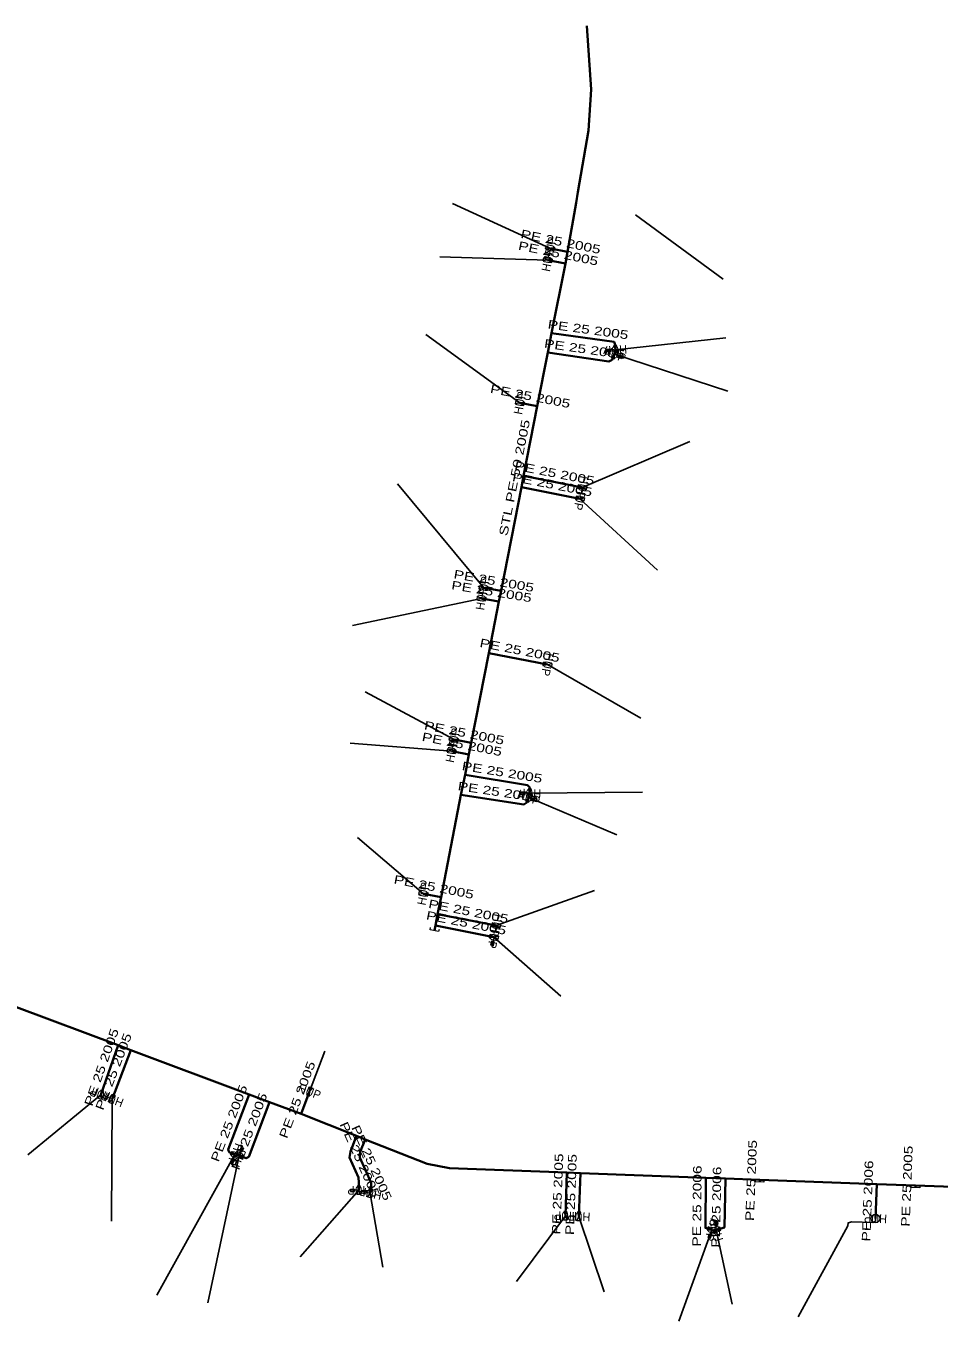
# Model space of a CAD drawing. Extents: x -737484 to -734496, y -1033882 to -1030666.
# Drawn here: x -736755 to -736648.9, y -1030928.9 to -1030778.3 of the extents above; entities that cross this region are included whole.
import ezdxf
from ezdxf.enums import TextEntityAlignment as Align

# ---------------------------------------------------------------- set-up
doc = ezdxf.new("R2010")
doc.units = 0
doc.header["$LTSCALE"] = 0.4
for name, color, linetype, lineweight in [('1', 7, 'Continuous', 13), ('22', 7, 'Continuous', 25), ('5', 7, 'Continuous', 35), ('7', 7, 'Continuous', 35)]:
    doc.layers.add(name, color=color, linetype=linetype, lineweight=lineweight)
doc.layers.add('2', color=7, linetype='Continuous')

msp = doc.modelspace()

# ---------------------------------------------------------------- linework, layer by layer
at = {"layer": '1'}
for p, q in [((-736687.048, -1030815.925), (-736687.397, -1030815.943)), ((-736686.47, -1030815.97), (-736686.969, -1030815.996)), ((-736686.57, -1030816.45), (-736686.113, -1030816.653)), ((-736686.075, -1030816.752), (-736685.755, -1030816.894)), ((-736697.022, -1030867.434), (-736697.371, -1030867.422)), ((-736696.45, -1030867.53), (-736696.949, -1030867.512)), ((-736696.55, -1030868.01), (-736696.083, -1030868.189)), ((-736696.04, -1030868.286), (-736695.713, -1030868.411)), ((-736700.61, -1030884.24), (-736700.705, -1030884.73)), ((-736700.793, -1030884.79), (-736700.86, -1030885.133)), ((-736730.993, -1030910.049), (-736731.13, -1030910.372)), ((-736730.7, -1030909.55), (-736730.895, -1030910.01)), ((-736730.21, -1030909.66), (-736730.03, -1030909.193)), ((-736729.933, -1030909.15), (-736729.808, -1030908.823)), ((-736716.865, -1030913.625), (-736717.215, -1030913.625)), ((-736716.29, -1030913.7), (-736716.79, -1030913.7)), ((-736715.526, -1030913.857), (-736715.869, -1030913.784)), ((-736714.98, -1030914.05), (-736715.469, -1030913.946)), ((-736674.705, -1030917.725), (-736674.705, -1030917.375)), ((-736675.51, -1030918.812), (-736675.607, -1030919.148)), ((-736675.28, -1030918.28), (-736675.417, -1030918.76)), ((-736674.78, -1030918.3), (-736674.78, -1030917.8))]:
    msp.add_line(p, q, dxfattribs=at)
for points in [[(-736694.57, -1030804.241), (-736694.487, -1030803.85), (-736693.592, -1030804.449), (-736693.509, -1030804.058)], [(-736694.858, -1030805.61), (-736694.782, -1030805.218), (-736693.877, -1030805.801), (-736693.801, -1030805.409)], [(-736687.468, -1030816.022), (-736687.476, -1030815.872), (-736686.977, -1030815.846), (-736686.969, -1030815.996)], [(-736687.468, -1030816.022), (-736687.46, -1030816.172), (-736686.961, -1030816.145), (-736686.969, -1030815.996)], [(-736687.432, -1030815.983), (-736687.436, -1030815.908), (-736687.012, -1030815.886), (-736687.008, -1030815.961)], [(-736686.549, -1030815.911), (-736686.183, -1030816.074), (-736686.956, -1030816.825), (-736686.59, -1030816.988)], [(-736686.244, -1030816.458), (-736686.643, -1030816.479), (-736686.296, -1030815.46), (-736686.695, -1030815.481)], [(-736685.656, -1030816.856), (-736685.717, -1030816.993), (-736686.174, -1030816.79), (-736686.113, -1030816.653)], [(-736685.656, -1030816.856), (-736685.595, -1030816.719), (-736686.052, -1030816.516), (-736686.113, -1030816.653)], [(-736685.706, -1030816.875), (-736685.736, -1030816.943), (-736686.124, -1030816.77), (-736686.094, -1030816.702)], [(-736698.098, -1030822.23), (-736698.022, -1030821.838), (-736697.117, -1030822.421), (-736697.041, -1030822.029)], [(-736689.811, -1030831.849), (-736689.887, -1030832.241), (-736690.792, -1030831.658), (-736690.868, -1030832.05)], [(-736690.071, -1030833.169), (-736690.147, -1030833.561), (-736691.052, -1030832.978), (-736691.128, -1030833.37)], [(-736702.307, -1030843.74), (-736702.237, -1030843.346), (-736701.322, -1030843.913), (-736701.252, -1030843.519)], [(-736702.555, -1030844.999), (-736702.492, -1030844.604), (-736701.567, -1030845.155), (-736701.504, -1030844.76)], [(-736693.851, -1030852.449), (-736693.927, -1030852.841), (-736694.832, -1030852.258), (-736694.908, -1030852.65)], [(-736705.768, -1030861.38), (-736705.692, -1030860.988), (-736704.787, -1030861.571), (-736704.711, -1030861.179)], [(-736706.028, -1030862.71), (-736705.952, -1030862.318), (-736705.047, -1030862.901), (-736704.971, -1030862.509)], [(-736697.449, -1030867.495), (-736697.454, -1030867.645), (-736696.954, -1030867.662), (-736696.949, -1030867.512)], [(-736697.449, -1030867.495), (-736697.444, -1030867.345), (-736696.944, -1030867.362), (-736696.949, -1030867.512)], [(-736697.41, -1030867.459), (-736697.407, -1030867.384), (-736696.982, -1030867.399), (-736696.985, -1030867.474)], [(-736696.557, -1030867.471), (-736696.184, -1030867.614), (-736696.915, -1030868.405), (-736696.542, -1030868.548)], [(-736696.267, -1030868.036), (-736696.667, -1030868.022), (-736696.232, -1030867.037), (-736696.632, -1030867.023)], [(-736695.616, -1030868.368), (-736695.67, -1030868.508), (-736696.136, -1030868.329), (-736696.083, -1030868.189)], [(-736695.665, -1030868.389), (-736695.692, -1030868.459), (-736696.088, -1030868.307), (-736696.061, -1030868.236)], [(-736695.616, -1030868.368), (-736695.562, -1030868.228), (-736696.029, -1030868.049), (-736696.083, -1030868.189)], [(-736709.318, -1030879.3), (-736709.242, -1030878.908), (-736708.337, -1030879.491), (-736708.261, -1030879.099)], [(-736699.821, -1030882.799), (-736699.897, -1030883.191), (-736700.802, -1030882.608), (-736700.878, -1030883)], [(-736700.081, -1030884.139), (-736700.157, -1030884.531), (-736701.062, -1030883.948), (-736701.138, -1030884.34)], [(-736700.8, -1030885.221), (-736700.948, -1030885.193), (-736700.852, -1030884.702), (-736700.705, -1030884.73)], [(-736700.829, -1030885.177), (-736700.903, -1030885.162), (-736700.822, -1030884.745), (-736700.748, -1030884.76)], [(-736700.8, -1030885.221), (-736700.653, -1030885.25), (-736700.558, -1030884.759), (-736700.705, -1030884.73)], [(-736746.253, -1030903.127), (-736746.631, -1030902.997), (-736745.928, -1030902.182), (-736746.306, -1030902.052)], [(-736722.037, -1030901.671), (-736721.664, -1030901.814), (-736722.395, -1030902.605), (-736722.022, -1030902.748)], [(-736744.962, -1030903.638), (-736745.335, -1030903.495), (-736744.604, -1030902.704), (-736744.977, -1030902.561)], [(-736730.161, -1030909.561), (-736730.317, -1030909.929), (-736731.082, -1030909.17), (-736731.238, -1030909.538)], [(-736731.09, -1030910.47), (-736731.228, -1030910.411), (-736731.033, -1030909.951), (-736730.895, -1030910.01)], [(-736731.109, -1030910.421), (-736731.178, -1030910.391), (-736731.012, -1030910), (-736730.943, -1030910.029)], [(-736731.09, -1030910.47), (-736730.952, -1030910.529), (-736730.757, -1030910.068), (-736730.895, -1030910.01)], [(-736730.748, -1030909.667), (-736730.605, -1030909.294), (-736729.814, -1030910.025), (-736729.671, -1030909.652)], [(-736729.851, -1030908.726), (-736729.991, -1030908.672), (-736730.17, -1030909.139), (-736730.03, -1030909.193)], [(-736729.851, -1030908.726), (-736729.711, -1030908.78), (-736729.89, -1030909.246), (-736730.03, -1030909.193)], [(-736729.83, -1030908.775), (-736729.76, -1030908.802), (-736729.912, -1030909.198), (-736729.983, -1030909.171)], [(-736717.29, -1030913.7), (-736717.29, -1030913.55), (-736716.79, -1030913.55), (-736716.79, -1030913.7)], [(-736717.29, -1030913.7), (-736717.29, -1030913.85), (-736716.79, -1030913.85), (-736716.79, -1030913.7)], [(-736717.252, -1030913.663), (-736717.252, -1030913.588), (-736716.827, -1030913.588), (-736716.827, -1030913.663)], [(-736716.09, -1030914.2), (-736716.49, -1030914.2), (-736716.09, -1030913.2), (-736716.49, -1030913.2)], [(-736715.958, -1030913.842), (-736715.989, -1030913.988), (-736715.5, -1030914.092), (-736715.469, -1030913.946)], [(-736715.958, -1030913.842), (-736715.926, -1030913.695), (-736715.437, -1030913.799), (-736715.469, -1030913.946)], [(-736715.913, -1030913.813), (-736715.897, -1030913.74), (-736715.481, -1030913.828), (-736715.497, -1030913.902)], [(-736714.888, -1030914.58), (-736715.279, -1030914.497), (-736714.68, -1030913.602), (-736715.071, -1030913.519)], [(-736692.117, -1030917.186), (-736692.517, -1030917.172), (-736692.082, -1030916.187), (-736692.482, -1030916.173)], [(-736690.547, -1030917.256), (-736690.947, -1030917.242), (-736690.512, -1030916.257), (-736690.912, -1030916.243)], [(-736674.78, -1030917.3), (-736674.93, -1030917.3), (-736674.93, -1030917.8), (-736674.78, -1030917.8)], [(-736674.78, -1030917.3), (-736674.63, -1030917.3), (-736674.63, -1030917.8), (-736674.78, -1030917.8)], [(-736674.743, -1030917.338), (-736674.668, -1030917.338), (-736674.668, -1030917.763), (-736674.743, -1030917.763)], [(-736674.744, -1030918.225), (-736674.854, -1030918.61), (-736675.705, -1030917.949), (-736675.815, -1030918.334)], [(-736675.555, -1030919.241), (-736675.699, -1030919.199), (-736675.562, -1030918.719), (-736675.417, -1030918.76)], [(-736675.58, -1030919.194), (-736675.652, -1030919.173), (-736675.535, -1030918.765), (-736675.463, -1030918.785)], [(-736675.555, -1030919.241), (-736675.411, -1030919.282), (-736675.273, -1030918.801), (-736675.417, -1030918.76)], [(-736675.205, -1030918.63), (-736675.315, -1030918.245), (-736674.244, -1030918.354), (-736674.354, -1030917.969)]]:
    msp.add_lwpolyline(points, close=True, dxfattribs=at)
for points in [[(-736706.978, -1030883.349), (-736707.03, -1030883.593), (-736708.009, -1030883.386), (-736707.957, -1030883.141)], [(-736669.201, -1030912.487), (-736669.21, -1030912.737), (-736670.209, -1030912.702), (-736670.2, -1030912.452)], [(-736651.091, -1030913.147), (-736651.1, -1030913.397), (-736652.099, -1030913.362), (-736652.09, -1030913.112)]]:
    msp.add_lwpolyline(points, dxfattribs=at)
msp.add_circle((-736656.2494, -1030916.9798), 0.5, dxfattribs=at)
at = {"layer": '22'}
for p, q in [((-736694.04, -1030804.15), (-736705.415, -1030798.929)), ((-736684.16, -1030800.24), (-736673.957, -1030807.751)), ((-736694.33, -1030805.51), (-736706.903, -1030805.13)), ((-736697.57, -1030822.13), (-736708.526, -1030814.186)), ((-736686.47, -1030815.97), (-736673.664, -1030814.556)), ((-736686.57, -1030816.45), (-736673.416, -1030820.757)), ((-736690.34, -1030831.95), (-736677.848, -1030826.608)), ((-736701.78, -1030843.63), (-736711.819, -1030831.546)), ((-736690.6, -1030833.27), (-736681.589, -1030841.573)), ((-736702.03, -1030844.88), (-736717.057, -1030848.008)), ((-736694.38, -1030852.55), (-736683.535, -1030858.783)), ((-736705.24, -1030861.28), (-736715.585, -1030855.733)), ((-736705.5, -1030862.61), (-736717.321, -1030861.686)), ((-736696.45, -1030867.53), (-736683.338, -1030867.391)), ((-736696.55, -1030868.01), (-736686.315, -1030872.352)), ((-736708.79, -1030879.2), (-736716.449, -1030872.681)), ((-736700.35, -1030882.9), (-736688.922, -1030878.836)), ((-736700.61, -1030884.24), (-736692.813, -1030891.107)), ((-736722.03, -1030902.21), (-736720.257, -1030897.535)), ((-736746.28, -1030902.59), (-736754.777, -1030909.56)), ((-736744.97, -1030903.1), (-736745.041, -1030917.296)), ((-736730.7, -1030909.55), (-736739.776, -1030925.889)), ((-736730.21, -1030909.66), (-736733.836, -1030926.768)), ((-736716.29, -1030913.7), (-736723.108, -1030921.449)), ((-736714.98, -1030914.05), (-736713.531, -1030922.646)), ((-736692.3, -1030916.68), (-736697.967, -1030924.293)), ((-736690.73, -1030916.75), (-736687.79, -1030925.49)), ((-736675.28, -1030918.28), (-736679.121, -1030928.908)), ((-736674.78, -1030918.3), (-736672.92, -1030926.923))]:
    msp.add_line(p, q, dxfattribs=at)
msp.add_lwpolyline([(-736656.25, -1030916.98), (-736656.26, -1030917.31), (-736656.54, -1030917.44), (-736659.01, -1030917.37), (-736659.43, -1030917.49), (-736659.46, -1030917.83), (-736665.23, -1030928.412)], dxfattribs=at)
at = {"layer": '5'}
for points in [[(-736689.8, -1030778.28), (-736689.31, -1030785.66), (-736689.6, -1030790.44), (-736690.85, -1030797.6), (-736691.05, -1030798.87), (-736692.03, -1030804.56), (-736692.3, -1030805.92), (-736693.9, -1030814.03), (-736694.33, -1030816.26), (-736695.56, -1030822.52), (-736697.15, -1030830.61), (-736697.41, -1030831.93), (-736699.77, -1030843.98), (-736700.03, -1030845.21), (-736701.19, -1030851.22), (-736703.24, -1030861.67), (-736703.5, -1030863), (-736703.96, -1030865.38), (-736704.43, -1030867.72), (-736706.75, -1030879.6), (-736707.14, -1030881.57), (-736707.4, -1030882.91), (-736707.52, -1030883.49)], [(-736756.09, -1030892.38), (-736744.26, -1030896.83), (-736742.79, -1030897.39), (-736729.03, -1030902.57), (-736726.69, -1030903.45), (-736723.02, -1030904.82), (-736716.57, -1030907.38), (-736715.58, -1030907.77), (-736708.37, -1030910.63), (-736705.78, -1030911.14), (-736692.11, -1030911.64), (-736690.54, -1030911.7), (-736675.97, -1030912.23), (-736673.68, -1030912.32), (-736669.7, -1030912.47), (-736656.1, -1030912.97), (-736651.59, -1030913.13), (-736634.32, -1030913.77), (-736631.2, -1030913.88), (-736626.82, -1030914.15)]]:
    msp.add_lwpolyline(points, dxfattribs=at)
at = {"layer": '7'}
for p, q in [((-736692.03, -1030804.56), (-736694.04, -1030804.15)), ((-736692.3, -1030805.92), (-736694.33, -1030805.51)), ((-736695.56, -1030822.52), (-736697.57, -1030822.13)), ((-736697.15, -1030830.61), (-736690.34, -1030831.95)), ((-736697.41, -1030831.93), (-736690.6, -1030833.27)), ((-736699.77, -1030843.98), (-736701.78, -1030843.63)), ((-736700.03, -1030845.21), (-736702.03, -1030844.88)), ((-736701.19, -1030851.22), (-736694.38, -1030852.55)), ((-736703.24, -1030861.67), (-736705.24, -1030861.28)), ((-736703.5, -1030863), (-736705.5, -1030862.61)), ((-736706.75, -1030879.6), (-736708.79, -1030879.2)), ((-736707.4, -1030882.91), (-736700.61, -1030884.24)), ((-736707.14, -1030881.57), (-736700.35, -1030882.9)), ((-736744.26, -1030896.83), (-736746.28, -1030902.59)), ((-736742.79, -1030897.39), (-736744.97, -1030903.1)), ((-736723.02, -1030904.82), (-736722.03, -1030902.21)), ((-736692.11, -1030911.64), (-736692.3, -1030916.68)), ((-736690.54, -1030911.7), (-736690.73, -1030916.75)), ((-736669.7, -1030912.47), (-736669.71, -1030912.72)), ((-736656.1, -1030912.97), (-736656.25, -1030916.98)), ((-736651.59, -1030913.13), (-736651.6, -1030913.38))]:
    msp.add_line(p, q, dxfattribs=at)
for points in [[(-736693.9, -1030814.03), (-736686.64, -1030815.02), (-736686.5, -1030815.39), (-736686.47, -1030815.97)], [(-736694.33, -1030816.26), (-736687.23, -1030817.29), (-736686.86, -1030817.11), (-736686.57, -1030816.45)], [(-736703.96, -1030865.38), (-736696.7, -1030866.57), (-736696.43, -1030866.87), (-736696.45, -1030867.53)], [(-736704.43, -1030867.72), (-736697.11, -1030868.82), (-736696.78, -1030868.6), (-736696.55, -1030868.01)], [(-736729.03, -1030902.57), (-736731.49, -1030908.96), (-736731.38, -1030909.26), (-736730.7, -1030909.55)], [(-736726.69, -1030903.45), (-736729.09, -1030909.8), (-736729.41, -1030909.97), (-736730.21, -1030909.66)], [(-736716.57, -1030907.38), (-736717.29, -1030909.19), (-736717.38, -1030909.89), (-736716.34, -1030912.22), (-736716.29, -1030912.79), (-736716.29, -1030913.7)], [(-736715.58, -1030907.77), (-736716.16, -1030909.23), (-736716.18, -1030909.89), (-736714.87, -1030912.81), (-736714.85, -1030913.46), (-736714.98, -1030914.05)], [(-736675.97, -1030912.23), (-736676.02, -1030918.07), (-736675.28, -1030918.28)], [(-736673.68, -1030912.32), (-736673.8, -1030918.02), (-736674.78, -1030918.3)]]:
    msp.add_lwpolyline(points, dxfattribs=at)

# ---------------------------------------------------------------- texts
at = {"layer": '2', "width": 0.95}
for rotation, p in [(78, (-736693.5502, -1030804.2535)), (79, (-736693.8389, -1030805.6049)), (336, (-736686.7729, -1030816.9067)), (183, (-736686.4963, -1030815.4705)), (79, (-736697.0789, -1030822.2249)), (259, (-736690.8301, -1030831.8541)), (259, (-736691.0901, -1030833.1741)), (81, (-736701.5355, -1030844.9577)), (80, (-736701.2866, -1030843.7163)), (259, (-736694.8701, -1030852.4541)), (79, (-736704.7489, -1030861.3749)), (79, (-736705.0089, -1030862.7049)), (339, (-736696.7287, -1030868.4763)), (178, (-736696.4321, -1030867.0297)), (79, (-736708.2989, -1030879.2949)), (259, (-736701.1001, -1030884.1441)), (259, (-736700.8401, -1030882.8041)), (161, (-736746.1167, -1030902.117)), (159, (-736744.7903, -1030902.6327)), (339, (-736722.2087, -1030902.6763)), (247, (-736731.1593, -1030909.3541)), (69, (-736729.7427, -1030909.8387)), (180, (-736716.2895, -1030913.2)), (168, (-736714.8755, -1030913.5602)), (178, (-736692.2821, -1030916.1797)), (178, (-736690.7121, -1030916.2497)), (254, (-736675.7598, -1030918.1417)), (106, (-736674.2988, -1030918.1613)), (178, (-736656.2321, -1030916.4797))]:
    msp.add_text('HUP', height=1, rotation=rotation, dxfattribs=at).set_placement(p, align=Align.CENTER)
at = {"layer": '5', "width": 1.4}
msp.add_text('STL PE 50 2005', height=1, rotation=78.857, dxfattribs=at).set_placement((-736697.7202, -1030830.9181), align=Align.CENTER)
at = {"layer": '7', "width": 1.35}
for s, rotation, p in [('PE 25 2005', 348.471, (-736692.9349, -1030803.8641)), ('PE 25 2005', 348.582, (-736693.2155, -1030805.224)), ('PE 25 2005', 352.235, (-736689.7181, -1030814.0954)), ('PE 25 2005', 351.746, (-736690.1478, -1030816.361)), ('PE 25 2005', 349.019, (-736696.4692, -1030821.834)), ('PE 25 2005', 348.868, (-736693.908, -1030832.1086)), ('PE 25 2005', 348.868, (-736693.648, -1030830.7886)), ('PE 25 2005', 350.122, (-736700.6888, -1030843.3123)), ('PE 25 2005', 350.631, (-736700.9479, -1030844.5513)), ('PE 25 2005', 348.949, (-736697.6888, -1030851.3939)), ('PE 25 2005', 348.966, (-736704.1437, -1030860.9835)), ('PE 25 2005', 348.966, (-736704.4037, -1030862.3135)), ('PE 25 2005', 350.691, (-736699.7234, -1030865.5672)), ('PE 25 2005', 351.454, (-736700.1863, -1030867.8512)), ('PE 25 2005', 348.906, (-736707.6737, -1030878.9084)), ('PE 25 2005', 348.917, (-736703.6486, -1030881.7435)), ('PE 25 2005', 348.917, (-736703.9086, -1030883.0835)), ('PE 25 2005', 70.675, (-736745.7409, -1030899.5445)), ('PE 25 2005', 69.104, (-736744.3464, -1030900.0658)), ('PE 25 2005', 69.228, (-736722.9922, -1030903.3373)), ('PE 25 2005', 68.944, (-736730.9159, -1030906.0786)), ('PE 25 2005', 69.296, (-736728.5733, -1030907.0188)), ('PE 25 2005', 294.054, (-736716.642, -1030910.3162)), ('PE 25 2005', 294.162, (-736715.2685, -1030910.6998)), ('PE 25 2005', 87.709, (-736670.2042, -1030912.5745)), ('PE 25 2005', 87.841, (-736692.7042, -1030914.1403)), ('PE 25 2005', 87.845, (-736691.1346, -1030914.2058)), ('PE 25 2005', 87.709, (-736652.0942, -1030913.2345)), ('PE 25 2006', 89.509, (-736676.4979, -1030915.5298)), ('PE 25 2006', 88.794, (-736674.25, -1030915.6685)), ('PE 25 2006', 87.858, (-736656.6746, -1030914.9557))]:
    msp.add_text(s, height=1, rotation=rotation, dxfattribs=at).set_placement(p, align=Align.CENTER)

doc.saveas('drawing.dxf')
